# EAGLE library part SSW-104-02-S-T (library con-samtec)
THROUGH-HOLE .025" SQ POST SOCKET Source: Samtec SSW.pdf
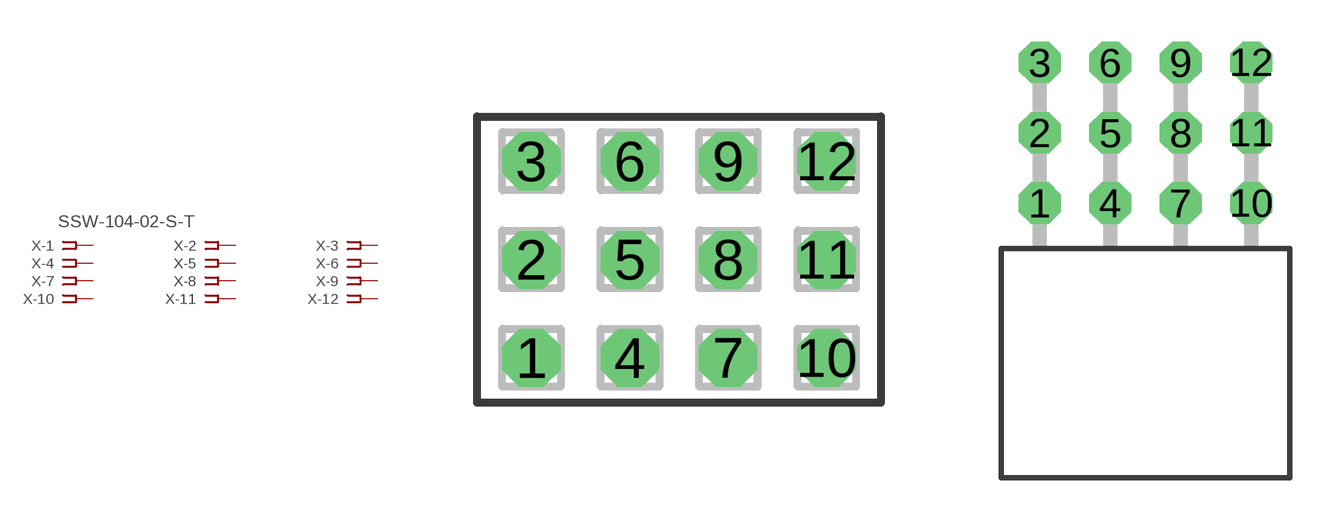
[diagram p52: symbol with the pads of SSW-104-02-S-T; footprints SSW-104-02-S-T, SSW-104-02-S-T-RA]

Designator prefix X; gates -1=FPINV -2=FPIN -3=FPIN -4=FPIN -5=FPIN -6=FPIN -7=FPIN -8=FPIN -9=FPIN -10=FPIN -11=FPIN -12=FPIN

## SSW-104-02-S-T (MPN: SSW-104-02-S-T; OC_FARNELL: unknown; OC_NEWARK: 82P2481)  [SSW-104-02-S-T]
1  -1:1  pas
2  -2:1  pas
3  -3:1  pas
4  -4:1  pas
5  -5:1  pas
6  -6:1  pas
7  -7:1  pas
8  -8:1  pas
9  -9:1  pas
10  -10:1  pas
11  -11:1  pas
12  -12:1  pas

## SSW-104-02-S-TRA (MPN: SSW-104-02-S-T-RA; OC_FARNELL: unknown; OC_NEWARK: 82P2482)  [SSW-104-02-S-T-RA]
Pads as for SSW-104-02-S-T

## Footprint SSW-104-02-S-T (pad centres in mm)
THROUGH-HOLE .025" SQ POST SOCKET Source: Samtec SSW.pdf
drill 1 pad 1.5 octagon: 1 -3.81,-2.54; 2 -3.81,0; 3 -3.81,2.54; 4 -1.27,-2.54; 5 -1.27,0; 6 -1.27,2.54; 7 1.27,-2.54; 8 1.27,0; 9 1.27,2.54; 10 3.81,-2.54; 11 3.81,0; 12 3.81,2.54

## Footprint SSW-104-02-S-T-RA (pad centres in mm)
THROUGH-HOLE .025" SQ POST SOCKET Source: Samtec SSW.pdf
drill 1 pad 1.5 octagon: 1 -3.81,1.524; 2 -3.81,4.064; 3 -3.81,6.604; 4 -1.27,1.524; 5 -1.27,4.064; 6 -1.27,6.604; 7 1.27,1.524; 8 1.27,4.064; 9 1.27,6.604; 10 3.81,1.524; 11 3.81,4.064; 12 3.81,6.604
